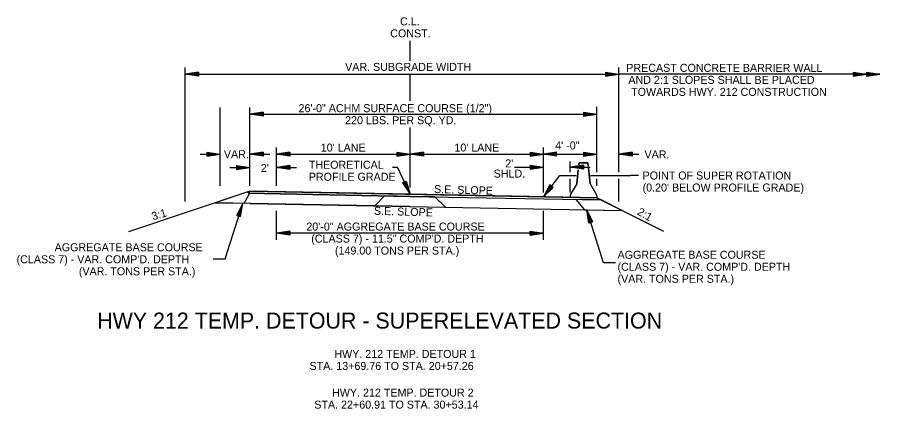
# Model space of a CAD drawing. Extents: x 138 to 3619, y -519 to 1449.
# Drawn here: x 2222 to 2868, y -366 to -73 of the extents above; entities that cross this region are included whole.
import ezdxf

# ---------------------------------------------------------------- set-up
doc = ezdxf.new("R2010")
doc.units = 0
for name, color, linetype in [('R_Annotation', 7, 'Continuous'), ('R_Barrier Wall', 7, 'Continuous'), ('R_Centerline', 7, 'Continuous'), ('R_Dimension', 7, 'Continuous')]:
    doc.layers.add(name, color=color, linetype=linetype)

msp = doc.modelspace()

# ---------------------------------------------------------------- linework, layer by layer
at = {"layer": 'R_Annotation'}
for p, q in [((2687.56, -191.66), (2681.56, -191.66)), ((2396.22, -203.44), (2305.24, -233.76)), ((2396.22, -203.44), (2394.89, -204.77)), ((2516.21, -207.34), (2394.89, -204.77)), ((2396.22, -203.44), (2656.21, -208.28)), ((2516.18, -214.86), (2370.17, -212.12)), ((2396.05, -212.61), (2675.26, -217.81)), ((2516.21, -207.34), (2659.6, -209.98)), ((2656.21, -208.28), (2706.21, -233.28))]:
    msp.add_line(p, q, dxfattribs=at)
at = {"layer": 'R_Barrier Wall'}
for points in [[(2642.34, -187.28), (2641.22, -197.88), (2636.3, -206.21), (2636.22, -207.88)], [(2641.21, -197.88), (2642.33, -187.3)], [(2649.83, -184.76), (2649.54, -182.05), (2642.89, -182.05), (2642.72, -183.66)], [(2642.72, -183.69), (2642.89, -182.05), (2649.54, -182.05), (2649.82, -184.7)], [(2649.97, -186.19), (2651.21, -197.88), (2656.13, -206.21), (2656.21, -207.88)], [(2651.22, -197.88), (2649.98, -186.19)]]:
    msp.add_lwpolyline(points, dxfattribs=at)
at = {"layer": 'R_Centerline'}
for p, q in [((2516.21, -105.68), (2516.21, -90.68)), ((2516.21, -135.68), (2516.21, -115.68)), ((2516.21, -200.68), (2516.21, -155.68))]:
    msp.add_line(p, q, dxfattribs=at)
at = {"layer": 'R_Dimension'}
for p, q in [((2347.63, -211.13), (2347.63, -110.68)), ((2357.63, -114.18), (2347.63, -115.68)), ((2347.63, -115.68), (2672.7, -115.68)), ((2357.63, -117.18), (2347.63, -115.68)), ((2357.63, -114.43), (2349.3, -115.68)), ((2357.63, -116.93), (2349.3, -115.68)), ((2357.63, -114.68), (2351.02, -115.68)), ((2357.63, -116.67), (2351.02, -115.68)), ((2357.63, -114.93), (2352.68, -115.68)), ((2357.63, -116.42), (2352.68, -115.68)), ((2357.63, -115.19), (2354.38, -115.68)), ((2357.63, -116.17), (2354.38, -115.68)), ((2357.63, -115.44), (2356.05, -115.68)), ((2357.63, -115.91), (2356.05, -115.68)), ((2357.63, -114.18), (2357.63, -117.18)), ((2662.7, -114.18), (2672.7, -115.68)), ((2662.7, -114.18), (2662.7, -117.18)), ((2662.7, -114.43), (2671.03, -115.68)), ((2662.7, -114.68), (2669.31, -115.68)), ((2662.7, -114.93), (2667.65, -115.68)), ((2662.7, -115.19), (2665.95, -115.68)), ((2662.7, -115.44), (2664.28, -115.68)), ((2662.7, -117.18), (2672.7, -115.68)), ((2662.7, -116.17), (2665.95, -115.68)), ((2662.7, -116.67), (2669.31, -115.68)), ((2662.7, -116.93), (2671.03, -115.68)), ((2662.7, -116.42), (2667.65, -115.68)), ((2662.7, -115.91), (2664.28, -115.68)), ((2672.7, -189.23), (2672.7, -110.68)), ((2868.35, -115.68), (2672.7, -115.68)), ((2848.35, -114.18), (2858.35, -115.68)), ((2848.35, -114.18), (2848.35, -117.18)), ((2848.35, -114.43), (2856.68, -115.68)), ((2848.35, -114.68), (2854.96, -115.68)), ((2848.35, -114.93), (2853.29, -115.68)), ((2848.35, -115.19), (2851.6, -115.68)), ((2848.35, -115.44), (2849.93, -115.68)), ((2848.35, -117.18), (2858.35, -115.68)), ((2848.35, -116.17), (2851.6, -115.68)), ((2848.35, -116.67), (2854.96, -115.68)), ((2848.35, -116.93), (2856.68, -115.68)), ((2848.35, -116.42), (2853.29, -115.68)), ((2848.35, -115.91), (2849.93, -115.68)), ((2858.35, -114.18), (2868.35, -115.68)), ((2858.35, -114.18), (2858.35, -117.18)), ((2858.35, -114.43), (2866.68, -115.68)), ((2858.35, -114.68), (2864.96, -115.68)), ((2858.35, -114.93), (2863.3, -115.68)), ((2858.35, -115.19), (2861.6, -115.68)), ((2858.35, -115.44), (2859.93, -115.68)), ((2858.35, -117.18), (2868.35, -115.68)), ((2858.35, -116.17), (2861.6, -115.68)), ((2858.35, -116.67), (2864.96, -115.68)), ((2858.35, -116.93), (2866.68, -115.68)), ((2858.35, -116.42), (2863.3, -115.68)), ((2858.35, -115.91), (2859.93, -115.68)), ((2373.78, -199.33), (2373.78, -140.68)), ((2396.22, -199.33), (2396.22, -140.68)), ((2656.21, -189.23), (2656.21, -140.16)), ((2406.22, -144.17), (2396.22, -145.67)), ((2396.22, -145.67), (2656.21, -145.67)), ((2406.22, -147.17), (2396.22, -145.67)), ((2406.22, -144.42), (2397.89, -145.67)), ((2406.22, -146.92), (2397.89, -145.67)), ((2406.22, -144.67), (2399.61, -145.67)), ((2406.22, -146.66), (2399.61, -145.67)), ((2406.22, -144.92), (2401.27, -145.67)), ((2406.22, -146.41), (2401.27, -145.67)), ((2406.22, -145.18), (2402.97, -145.67)), ((2406.22, -146.16), (2402.97, -145.67)), ((2406.22, -145.43), (2404.64, -145.67)), ((2406.22, -145.9), (2404.64, -145.67)), ((2406.22, -144.17), (2406.22, -147.17)), ((2646.21, -144.17), (2656.21, -145.67)), ((2646.21, -144.17), (2646.21, -147.17)), ((2646.21, -144.42), (2654.54, -145.67)), ((2646.21, -144.67), (2652.82, -145.67)), ((2646.21, -144.92), (2651.15, -145.67)), ((2646.21, -145.18), (2649.46, -145.67)), ((2646.21, -145.43), (2647.79, -145.67)), ((2646.21, -147.17), (2656.21, -145.67)), ((2646.21, -146.16), (2649.46, -145.67)), ((2646.21, -146.66), (2652.82, -145.67)), ((2646.21, -146.92), (2654.54, -145.67)), ((2646.21, -146.41), (2651.15, -145.67)), ((2646.21, -145.9), (2647.79, -145.67)), ((2363.78, -174.18), (2373.78, -175.68)), ((2363.78, -174.18), (2363.78, -177.18)), ((2363.78, -174.43), (2372.11, -175.68)), ((2406.22, -174.18), (2396.22, -175.68)), ((2406.22, -174.43), (2397.89, -175.68)), ((2406.22, -174.18), (2406.22, -177.18)), ((2416.22, -199.33), (2416.22, -170.68)), ((2426.22, -174.18), (2416.22, -175.68)), ((2426.22, -174.43), (2417.89, -175.68)), ((2426.22, -174.18), (2426.22, -177.18)), ((2506.21, -174.18), (2516.21, -175.68)), ((2506.21, -174.18), (2506.21, -177.18)), ((2506.21, -174.43), (2514.54, -175.68)), ((2526.21, -174.18), (2516.21, -175.68)), ((2526.21, -174.43), (2517.88, -175.68)), ((2526.21, -174.18), (2526.21, -177.18)), ((2606.21, -174.18), (2616.21, -175.68)), ((2606.21, -174.18), (2606.21, -177.18)), ((2606.21, -174.43), (2614.54, -175.68)), ((2616.21, -204.4), (2616.21, -170.68)), ((2626.21, -174.18), (2616.21, -175.68)), ((2626.21, -174.43), (2617.88, -175.68)), ((2646.21, -174.18), (2656.21, -175.68)), ((2646.21, -174.18), (2646.21, -177.18)), ((2646.21, -174.43), (2654.54, -175.68)), ((2682.7, -174.18), (2672.7, -175.68)), ((2682.7, -174.43), (2674.37, -175.68)), ((2682.7, -174.18), (2682.7, -177.18)), ((2358.78, -175.68), (2373.78, -175.68)), ((2363.78, -174.68), (2370.39, -175.68)), ((2363.78, -174.93), (2368.72, -175.68)), ((2363.78, -175.19), (2367.03, -175.68)), ((2363.78, -175.44), (2365.36, -175.68)), ((2363.78, -177.18), (2373.78, -175.68)), ((2363.78, -176.17), (2367.03, -175.68)), ((2363.78, -176.67), (2370.39, -175.68)), ((2363.78, -176.93), (2372.11, -175.68)), ((2363.78, -176.42), (2368.72, -175.68)), ((2363.78, -175.91), (2365.36, -175.68)), ((2396.19, -175.68), (2411.19, -175.68)), ((2406.22, -177.18), (2396.22, -175.68)), ((2406.22, -176.93), (2397.89, -175.68)), ((2406.22, -174.68), (2399.61, -175.68)), ((2406.22, -176.67), (2399.61, -175.68)), ((2406.22, -174.93), (2401.27, -175.68)), ((2406.22, -176.42), (2401.27, -175.68)), ((2406.22, -175.19), (2402.97, -175.68)), ((2406.22, -176.17), (2402.97, -175.68)), ((2406.22, -175.44), (2404.64, -175.68)), ((2406.22, -175.91), (2404.64, -175.68)), ((2416.22, -175.68), (2656.21, -175.68)), ((2426.22, -177.18), (2416.22, -175.68)), ((2426.22, -176.93), (2417.89, -175.68)), ((2426.22, -174.68), (2419.61, -175.68)), ((2426.22, -176.67), (2419.61, -175.68)), ((2426.22, -174.93), (2421.27, -175.68)), ((2426.22, -176.42), (2421.27, -175.68)), ((2426.22, -175.19), (2422.97, -175.68)), ((2426.22, -176.17), (2422.97, -175.68)), ((2426.22, -175.44), (2424.64, -175.68)), ((2426.22, -175.91), (2424.64, -175.68)), ((2506.21, -174.68), (2512.82, -175.68)), ((2506.21, -174.93), (2511.15, -175.68)), ((2506.21, -175.19), (2509.46, -175.68)), ((2506.21, -175.44), (2507.79, -175.68)), ((2506.21, -177.18), (2516.21, -175.68)), ((2506.21, -176.17), (2509.46, -175.68)), ((2506.21, -176.67), (2512.82, -175.68)), ((2506.21, -176.93), (2514.54, -175.68)), ((2506.21, -176.42), (2511.15, -175.68)), ((2506.21, -175.91), (2507.79, -175.68)), ((2526.21, -177.18), (2516.21, -175.68)), ((2526.21, -176.93), (2517.88, -175.68)), ((2526.21, -174.68), (2519.6, -175.68)), ((2526.21, -176.67), (2519.6, -175.68)), ((2526.21, -174.93), (2521.26, -175.68)), ((2526.21, -176.42), (2521.26, -175.68)), ((2526.21, -175.19), (2522.96, -175.68)), ((2526.21, -176.17), (2522.96, -175.68)), ((2526.21, -175.44), (2524.63, -175.68)), ((2526.21, -175.91), (2524.63, -175.68)), ((2606.21, -174.68), (2612.82, -175.68)), ((2606.21, -174.93), (2611.15, -175.68)), ((2606.21, -175.19), (2609.46, -175.68)), ((2606.21, -175.44), (2607.79, -175.68)), ((2606.21, -177.18), (2616.21, -175.68)), ((2606.21, -176.17), (2609.46, -175.68)), ((2606.21, -176.67), (2612.82, -175.68)), ((2606.21, -176.93), (2614.54, -175.68)), ((2606.21, -176.42), (2611.15, -175.68)), ((2606.21, -175.91), (2607.79, -175.68)), ((2626.21, -177.18), (2616.21, -175.68)), ((2626.21, -176.93), (2617.88, -175.68)), ((2626.21, -174.68), (2619.6, -175.68)), ((2626.21, -176.67), (2619.6, -175.68)), ((2626.21, -174.93), (2621.26, -175.68)), ((2626.21, -176.42), (2621.26, -175.68)), ((2626.21, -175.19), (2622.96, -175.68)), ((2626.21, -176.17), (2622.96, -175.68)), ((2626.21, -175.44), (2624.63, -175.68)), ((2626.21, -175.91), (2624.63, -175.68)), ((2646.21, -174.68), (2652.82, -175.68)), ((2646.21, -174.93), (2651.15, -175.68)), ((2646.21, -175.19), (2649.46, -175.68)), ((2646.21, -175.44), (2647.79, -175.68)), ((2646.21, -177.18), (2656.21, -175.68)), ((2646.21, -176.17), (2649.46, -175.68)), ((2646.21, -176.67), (2652.82, -175.68)), ((2646.21, -176.93), (2654.54, -175.68)), ((2646.21, -176.42), (2651.15, -175.68)), ((2646.21, -175.91), (2647.79, -175.68)), ((2672.7, -175.68), (2687.7, -175.68)), ((2682.7, -177.18), (2672.7, -175.68)), ((2682.7, -176.93), (2674.37, -175.68)), ((2682.7, -174.68), (2676.09, -175.68)), ((2682.7, -176.67), (2676.09, -175.68)), ((2682.7, -174.93), (2677.76, -175.68)), ((2682.7, -176.42), (2677.76, -175.68)), ((2682.7, -175.19), (2679.45, -175.68)), ((2682.7, -176.17), (2679.45, -175.68)), ((2682.7, -175.44), (2681.12, -175.68)), ((2682.7, -175.91), (2681.12, -175.68)), ((2381.22, -185.68), (2396.22, -185.68)), ((2386.22, -184.18), (2396.22, -185.68)), ((2386.22, -184.18), (2386.22, -187.18)), ((2386.22, -184.43), (2394.55, -185.68)), ((2386.22, -184.68), (2392.83, -185.68)), ((2386.22, -184.93), (2391.16, -185.68)), ((2386.22, -185.19), (2389.47, -185.68)), ((2386.22, -185.44), (2387.8, -185.68)), ((2386.22, -187.18), (2396.22, -185.68)), ((2386.22, -186.17), (2389.47, -185.68)), ((2386.22, -186.67), (2392.83, -185.68)), ((2386.22, -186.93), (2394.55, -185.68)), ((2386.22, -186.42), (2391.16, -185.68)), ((2386.22, -185.91), (2387.8, -185.68)), ((2426.2, -184.18), (2416.2, -185.68)), ((2426.2, -187.18), (2416.2, -185.68)), ((2416.2, -185.68), (2431.2, -185.68)), ((2426.2, -184.43), (2417.87, -185.68)), ((2426.2, -186.93), (2417.87, -185.68)), ((2426.2, -184.68), (2419.59, -185.68)), ((2426.2, -186.67), (2419.59, -185.68)), ((2426.2, -184.93), (2421.25, -185.68)), ((2426.2, -186.42), (2421.25, -185.68)), ((2426.2, -185.19), (2422.95, -185.68)), ((2426.2, -186.17), (2422.95, -185.68)), ((2426.2, -185.44), (2424.62, -185.68)), ((2426.2, -185.91), (2424.62, -185.68)), ((2426.2, -184.18), (2426.2, -187.18)), ((2502.97, -185.35), (2506.93, -185.35)), ((2594.47, -185.34), (2616.21, -185.34)), ((2606.21, -183.84), (2616.21, -185.34)), ((2606.21, -183.84), (2606.21, -186.84)), ((2606.21, -184.09), (2614.54, -185.34)), ((2606.21, -184.35), (2612.82, -185.34)), ((2606.21, -184.6), (2611.15, -185.34)), ((2606.21, -184.86), (2609.46, -185.34)), ((2606.21, -185.11), (2607.79, -185.34)), ((2606.21, -186.84), (2616.21, -185.34)), ((2606.21, -185.83), (2609.46, -185.34)), ((2606.21, -186.34), (2612.82, -185.34)), ((2606.21, -186.59), (2614.54, -185.34)), ((2606.21, -186.09), (2611.15, -185.34)), ((2606.21, -185.58), (2607.79, -185.34)), ((2646.19, -183.84), (2636.19, -185.34)), ((2646.19, -186.84), (2636.19, -185.34)), ((2636.19, -185.34), (2651.19, -185.34)), ((2636.21, -189.23), (2636.21, -181.19)), ((2646.19, -184.09), (2637.86, -185.34)), ((2646.19, -186.59), (2637.86, -185.34)), ((2646.19, -184.35), (2639.58, -185.34)), ((2646.19, -186.34), (2639.58, -185.34)), ((2646.19, -184.6), (2641.24, -185.34)), ((2646.19, -186.09), (2641.24, -185.34)), ((2646.19, -184.86), (2642.94, -185.34)), ((2646.19, -185.83), (2642.94, -185.34)), ((2646.19, -185.11), (2644.61, -185.34)), ((2646.19, -185.58), (2644.61, -185.34)), ((2646.19, -183.84), (2646.19, -186.84)), ((2510.69, -197.2), (2513.42, -195.96)), ((2510.69, -197.2), (2516.21, -205.68)), ((2510.92, -197.1), (2515.51, -204.16)), ((2511.15, -196.99), (2514.8, -202.59)), ((2511.38, -196.89), (2514.11, -201.08)), ((2511.61, -196.78), (2513.4, -199.54)), ((2511.84, -196.68), (2512.71, -198.02)), ((2512.27, -196.48), (2512.71, -198.02)), ((2512.5, -196.38), (2513.4, -199.54)), ((2512.73, -196.27), (2514.11, -201.08)), ((2512.96, -196.17), (2514.8, -202.59)), ((2513.19, -196.06), (2515.51, -204.16)), ((2513.42, -195.96), (2516.21, -205.68)), ((2621.13, -198.74), (2616.18, -207.57)), ((2621.32, -198.9), (2617.21, -206.25)), ((2623.3, -200.43), (2617.21, -206.25)), ((2621.53, -199.05), (2618.26, -204.89)), ((2623.1, -200.27), (2618.26, -204.89)), ((2621.72, -199.21), (2619.28, -203.57)), ((2622.9, -200.12), (2619.28, -203.57)), ((2621.92, -199.36), (2620.32, -202.23)), ((2622.69, -199.96), (2620.32, -202.23)), ((2623.5, -200.58), (2621.13, -198.74)), ((2622.13, -199.52), (2621.34, -200.91)), ((2622.5, -199.81), (2621.34, -200.91)), ((2636.21, -204.4), (2636.21, -194.21)), ((2656.21, -199.33), (2656.21, -194.21)), ((2672.7, -211.13), (2672.7, -194.21)), ((2396.22, -203.44), (2370.17, -212.12)), ((2396.22, -203.44), (2394.89, -204.77)), ((2394.89, -204.77), (2396.22, -203.44)), ((2394.89, -204.77), (2516.21, -207.34)), ((2516.21, -205.68), (2396.22, -203.44)), ((2496.99, -206.87), (2489.82, -214.36)), ((2516.21, -207.31), (2496.99, -206.87)), ((2656.21, -208.28), (2516.21, -205.68)), ((2623.5, -200.58), (2616.18, -207.57)), ((2370.17, -212.12), (2391.81, -212.49)), ((2386.3, -221.59), (2390.75, -212.51)), ((2389.16, -222.49), (2390.75, -212.51)), ((2534.91, -207.69), (2516.21, -207.31)), ((2516.21, -207.34), (2659.6, -209.98)), ((2542.76, -215.37), (2534.91, -207.69)), ((2659.6, -209.98), (2640.52, -209.63)), ((2640.52, -209.63), (2646.89, -217.28)), ((2659.6, -209.98), (2656.21, -208.28)), ((2675.26, -217.81), (2659.6, -209.98)), ((2386.54, -221.66), (2390.25, -214.1)), ((2386.78, -221.74), (2389.73, -215.74)), ((2387.02, -221.81), (2389.22, -217.32)), ((2387.27, -221.89), (2388.71, -218.94)), ((2388.2, -222.19), (2388.71, -218.94)), ((2388.44, -222.26), (2389.22, -217.32)), ((2388.68, -222.34), (2389.73, -215.74)), ((2388.92, -222.42), (2390.25, -214.1)), ((2416.22, -239.88), (2416.22, -218.18)), ((2489.82, -214.36), (2516.18, -214.87)), ((2516.18, -214.87), (2542.76, -215.37)), ((2616.21, -239.88), (2616.21, -218.18)), ((2646.89, -217.28), (2675.26, -217.81)), ((2653.21, -226.43), (2648.82, -217.32)), ((2650.34, -227.31), (2648.82, -217.32)), ((2652.97, -226.5), (2649.31, -218.91)), ((2650.58, -227.24), (2649.31, -218.91)), ((2386.3, -221.59), (2389.16, -222.49)), ((2387.5, -221.97), (2388.21, -220.53)), ((2387.95, -222.11), (2388.21, -220.53)), ((2650.82, -227.16), (2649.82, -220.56)), ((2652.73, -226.58), (2649.82, -220.56)), ((2652.49, -226.65), (2650.31, -222.15)), ((2651.06, -227.09), (2650.31, -222.15)), ((2651.31, -227.02), (2650.81, -223.77)), ((2652.24, -226.73), (2650.81, -223.77)), ((2651.55, -226.94), (2651.31, -225.36)), ((2652, -226.8), (2651.31, -225.36)), ((2653.21, -226.43), (2650.34, -227.31)), ((2426.22, -233.38), (2416.22, -234.88)), ((2616.21, -234.88), (2416.22, -234.88)), ((2426.22, -236.38), (2416.22, -234.88)), ((2426.22, -233.63), (2417.89, -234.88)), ((2426.22, -236.13), (2417.89, -234.88)), ((2426.22, -233.89), (2419.61, -234.88)), ((2426.22, -235.88), (2419.61, -234.88)), ((2426.22, -234.14), (2421.27, -234.88)), ((2426.22, -235.63), (2421.27, -234.88)), ((2426.22, -234.4), (2422.97, -234.88)), ((2426.22, -235.37), (2422.97, -234.88)), ((2426.22, -234.65), (2424.64, -234.88)), ((2426.22, -235.12), (2424.64, -234.88)), ((2426.22, -233.38), (2426.22, -236.38)), ((2606.21, -233.38), (2616.21, -234.88)), ((2606.21, -236.38), (2606.21, -233.38)), ((2606.21, -233.63), (2614.54, -234.88)), ((2606.21, -233.89), (2612.82, -234.88)), ((2606.21, -234.14), (2611.15, -234.88)), ((2606.21, -234.39), (2609.46, -234.88)), ((2606.21, -234.65), (2607.79, -234.88)), ((2606.21, -236.38), (2616.21, -234.88)), ((2606.21, -235.37), (2609.46, -234.88)), ((2606.21, -235.88), (2612.82, -234.88)), ((2606.21, -236.13), (2614.54, -234.88)), ((2606.21, -235.63), (2611.15, -234.88)), ((2606.21, -235.12), (2607.79, -234.88))]:
    msp.add_line(p, q, dxfattribs=at)
for points in [[(2516.21, -205.68), (2506.93, -185.35)], [(2616.18, -207.57), (2628.52, -191.66), (2640.86, -191.66)], [(2651.46, -191.66), (2681.56, -191.66)], [(2651.46, -191.66), (2651.46, -191.66)], [(2391.81, -212.49), (2396.17, -204.79), (2394.89, -204.77)], [(2368.67, -253.98), (2377.66, -253.98), (2390.75, -212.51)], [(2670.27, -257.03), (2661.28, -257.03), (2648.82, -217.32)]]:
    msp.add_lwpolyline(points, dxfattribs=at)

# ---------------------------------------------------------------- texts
at = {"layer": 'R_Annotation'}
for s, height, p in [('C.L.', 6, (2508.74, -79.13)), ('CONST.', 6, (2501.37, -88.13)), ('VAR. SUBGRADE WIDTH', 6, (2467.55, -113.25)), ('PRECAST CONCRETE BARRIER WALL', 6, (2678.32, -113.97)), ('AND 2:1 SLOPES SHALL BE PLACED', 6, (2679.91, -122.97)), ('TOWARDS HWY. 212 CONSTRUCTION', 6, (2681.99, -131.97)), ('26\'-0" ACHM SURFACE COURSE (1/2")', 6, (2432.63, -144.18)), ('220 LBS. PER SQ. YD. ', 6, (2467.55, -153.18)), ("10' LANE", 6, (2449.29, -173.71)), ("10' LANE", 6, (2549.48, -173.71)), ('4\' -0"', 6, (2625.05, -172.08)), ('VAR.', 6, (2376.66, -178.68)), ('VAR.', 6, (2691.97, -178.85)), ('THEORETICAL', 6, (2440.31, -186.59)), ("2'", 6, (2587.62, -185.59)), ("2'", 6, (2404.34, -188.98)), ('SHLD.', 6, (2578.88, -193.21)), ('PROFILE GRADE', 6, (2440.31, -195.59)), ('POINT OF SUPER ROTATION', 6, (2690.56, -194.66)), ("(0.20' BELOW PROFILE GRADE)", 6, (2690.56, -203.66)), ('20\'-0" AGGREGATE BASE COURSE', 6, (2438.48, -232.92)), ('(CLASS 7) - 11.5" COMP\'D. DEPTH', 6, (2442.16, -241.92)), ('AGGREGATE BASE COURSE', 6, (2249.79, -248.44)), ('(149.00 TONS PER STA.)', 6, (2459.93, -250.92)), ("(CLASS 7) - VAR. COMP'D. DEPTH", 6, (2221.26, -257.44)), ('AGGREGATE BASE COURSE', 6, (2671.77, -254.05)), ("(CLASS 7) - VAR. COMP'D. DEPTH", 6, (2671.77, -263.05)), ('(VAR. TONS PER STA.)', 6, (2267.93, -266.44)), ('(VAR. TONS PER STA.)', 6, (2671.77, -272.05)), ('HWY 212 TEMP. DETOUR - SUPERELEVATED SECTION', 12, (2281.65, -306.37)), ('HWY. 212 TEMP. DETOUR 1', 6, (2459.47, -328.37)), ('STA. 13+69.76 TO STA. 20+57.26', 6, (2440.84, -337.37)), ('HWY. 212 TEMP. DETOUR 2', 6, (2457.77, -357.37)), ('STA. 22+60.91 TO STA. 30+53.14', 6, (2444.45, -366.37))]:
    msp.add_text(s, height=height, dxfattribs=at).set_placement(p)
for s, rotation, p in [('S.E. SLOPE', 358.26086, (2534.17, -204.74)), ('3:1', 16.83249, (2323.57, -225.31)), ('S.E. SLOPE', 358.26086, (2489.1, -221.04)), ('2:1', 330.43118, (2686.01, -220.57))]:
    msp.add_text(s, height=6, rotation=rotation, dxfattribs=at).set_placement(p)

doc.saveas('drawing.dxf')
